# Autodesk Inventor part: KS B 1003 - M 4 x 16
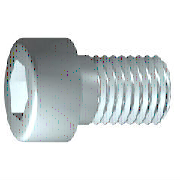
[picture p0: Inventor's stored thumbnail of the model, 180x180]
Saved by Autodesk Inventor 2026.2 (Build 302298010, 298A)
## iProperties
Created: 2025-01
Part Number: KS B 1003 - M 4 x 16
Material: 강철, 연강
Description: 6각머리 태핑 나사
Document SubType Name: Modeling
Standard: KS B 1003
Designer: work
Standards Organization: KS
Language: ko-KR
Size Designation: M 4 x 16
Categories: <MemberInstance><Categories><Category DisplayName="조임쇠" InternalName="e4da775c-781d-43d5-af7c-5136215cf5a6" Mnemonic="FSTN"><Category DisplayName="볼트" InternalN
Density: 7.85 g/cm^3
Appearance: 반연마
Author: work
IsCustomPart: 1
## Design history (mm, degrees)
body "Solid1"
workplane "Work Plane1"
fillet "Fillet2" dims "d30" = 0.1 (= R)
revolve "본체" stored, may be unused: angle "d10" = 90 deg
sketch "스케치2"
  geometry: L1 (0, -4.9)-(0, 4.9) reference; L2 (-4.9, 0)-(4.9, 0) reference; L3 (1.732, 0)-(0.866, -1.5); L4 (0.866, -1.5)-(-0.866, -1.5); L5 (-0.866, -1.5)-(-1.732, 0); L6 (-1.732, 0)-(-0.866, 1.5); L7 (-0.866, 1.5)-(0.866, 1.5); L8 (0.866, 1.5)-(1.732, 0); 2 further points
  constraints: 12 end point, 1 coincident, 1 horizontal alignment, 1 point on line, 12 other
extrude "슬롯" join sketch "스케치2" stored distance "d11" = 10; taper "d12" = 0 deg
fillet "모깎기1" dims "d17" = 0.4 (= RR)
feature "스레드" dims "d13" = 14.25 (= GEL), "d14" = 0
chamfer "모따기1" distance "d15" = 0.42941 (= -0.5 x SPD + 0.5 x GD); stored, may be unused: second distance "d16" = 0.42941 (= GUL), angle "d27" = 45 deg
sketch "스케치1"
  geometry: L1 (-1, 0)-(16, 0); L2 (16, 0)-(16, 2); L3 (16, 2)-(1.75, 2); L4 (1.75, 2)-(1.32, 2); L5 (1.32, 2)-(0, 2); L6 (0, 2)-(0, 3.5); L7 (0, 3.5)-(-4, 3.5); L8 (-4, 3.5)-(-4, 1.732); L9 (-4, 1.732)-(-2, 1.732); L10 (-2, 1.732)-(-1, 0); L11 (-8, 0)-(20, 0) reference; L12 (0, -0.7)-(0, 4.2) reference; L13 (1.75, 2)-(0, 2)
  constraints: 22 end point, 6 parallel, 2 collinear, 2 perpendicular, 1 horizontal, 1 point on line
  dimensions: "d1" = 14.25 distance from line of L3.end L2 (= GEL); "d2" = 0.42952 distance of L4.end L3.end (computed from GAL); "d3" = 4 distance between parallel lines of L8 L6 (= KOH); "d4" = 2 distance of L8.end L9.end (= INTI); "d5" = 60 deg angle of L10 L1; "d6" = 4 diameter of L3 L1 (= GD); "d7" = 4 diameter of L5 L1 (= BDM); "d8" = 3.4641 diameter of L9 L1 (= 1.1547 x SW); "d9" = 7 diameter of L7 L1 (= KOD); "d26" = 16 distance between parallel lines of L12 L2 (= NLG)
other parameters: "GD" = 4 (= NND) [user parameter; used in 2 equation terms], "NLG" = 16 [user parameter; used in 1 equation term], "GEL" = 14.25 [user parameter; used in 2 equation terms], "KOD" = 7 [user parameter; used in 1 equation term], "KOH" = 4 [user parameter; used in 1 equation term], "INTI" = 2 [user parameter; used in 1 equation term], "GAL" = 0.42941 (= 0.61345 x PTC) [user parameter; used in 1 equation term], "GUL" = 0.42941 (= 0.61345 x PTC) [user parameter; used in 1 equation term], "BDM" = 4 (= NND) [user parameter; used in 1 equation term], "SW" = 3 [user parameter; used in 2 equation terms], "RR" = 0.4 [user parameter; used in 1 equation term], "SPD" = 3.14117 (= NND - 1.2269 x PTC) [user parameter; used in 1 equation term], "d19" = 0, "d28" = 0, "d29" = 0, "R" = 0.1 [user parameter; used in 1 equation term], "PHH" = 0.2 [user parameter], "GD1" = 3.14117 (= THREADDIA - 1.2269 x PTC) [user parameter], "THREADDIA" = 4 [user parameter; used in 1 equation term], "FAWI" = 45 deg [user parameter], "TPU" = 14.28571 (computed from PTC) [user parameter], "PTC" = 0.7 [user parameter; used in 5 equation terms], "NND" = 4 [user parameter; used in 3 equation terms], "TOA" = 30 deg [user parameter], "E0" = 3.465 (= 1.155 x SW) [user parameter]
